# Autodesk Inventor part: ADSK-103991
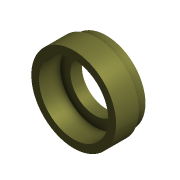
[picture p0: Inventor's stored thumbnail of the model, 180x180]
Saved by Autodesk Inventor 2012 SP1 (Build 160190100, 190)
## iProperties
Shininess: 0.0
Created: 2000-11
Part Number: ADSK-103991
Document SubType Name: Modeling
Stock Number: ADSK-103991
Density: 1 g/cm^3
Material: Default
Density: 0.0
Volumn: 0.0
Area: 0.0
PropertySet Name: Model Information
Control State: 0
Master: False
Checked Out: False
Author: gao
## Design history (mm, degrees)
node "Extrusion1" dims "d2" = 63.5, "d3" = 0
  sketch "Sketch1"
    geometry: C1 r 47.625 at (0, 0); C2 r 82.55 at (0, 0)
    constraints: 2 centre point, 1 coincident
    dimensions: "d0" = 165.1 diameter of C2; "d1" = 95.25 diameter of C1
node "Extrusion2" dims "d5" = 41.275, "d6" = 0
  sketch "Sketch2"
    geometry: C1 r 47.625 at (0, 0) reference; C2 r 82.55 at (0, 0) reference; C3 r 67.374 at (0, 0)
    constraints: 1 centre point, 1 coincident
    dimensions: "d4" = 134.747 diameter of C3
node "Extrusion3" dims "d8" = 19.05, "d9" = 0
  sketch "Sketch3"
    geometry: C1 r 82.55 at (0, 0) reference; C2 r 76.2 at (0, 0)
    constraints: 1 centre point, 1 coincident
    dimensions: "d7" = 152.4 diameter of C2
body "Solid1"
